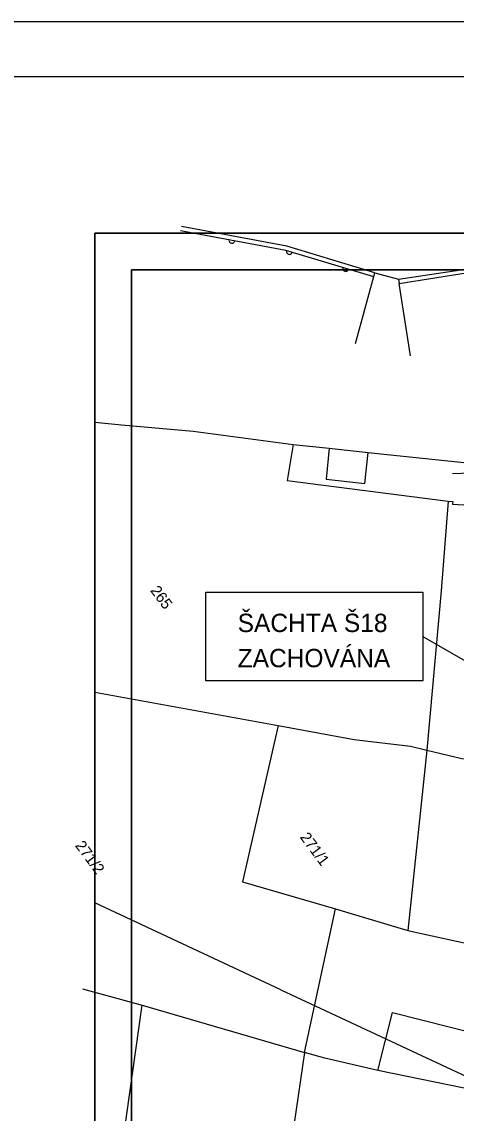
# Model space of a CAD drawing. Extents: x -601580 to 4, y -1204314 to 4.
# Drawn here: x -596081 to -596051.4, y -1202950 to -1202875.6 of the extents above; entities that cross this region are included whole.
import ezdxf

# ---------------------------------------------------------------- set-up
doc = ezdxf.new("R2010")
doc.units = 0
for name, color, linetype in [('00-KN-HRANICE PARCEL', 7, 'Continuous'), ('00-KN-PARC. CISLA', 7, 'Continuous'), ('00-KN-VNITRNI KRESBA', 7, 'Continuous'), ('00-POLOHOPIS', 7, 'Continuous'), ('00-RAZÍTKO', 7, 'Continuous'), ('00-SITE KOM. KABEL', 7, 'Continuous'), ('11-REKONSTRUKCE KANALIZACE', 7, 'Continuous'), ('11-REKONSTRUKCE KANALIZACE OSA', 7, 'Continuous')]:
    doc.layers.add(name, color=color, linetype=linetype)

msp = doc.modelspace()

# ---------------------------------------------------------------- linework, layer by layer
for points in [[(-595979.871, -1202875.568), (-596202.621, -1202875.568), (-596202.621, -1203190.718), (-595979.871, -1203190.718)], [(-595976.121, -1202879.318), (-596198.871, -1202879.318), (-596198.871, -1203186.968), (-595976.121, -1203186.968)], [(-595970.972, -1202892.468), (-595970.972, -1202889.968), (-596076.023, -1202889.968), (-596076.023, -1203038.468), (-595970.972, -1203038.468), (-595970.972, -1203035.968)], [(-595973.472, -1202892.468), (-596073.523, -1202892.468), (-596073.523, -1203035.968), (-595973.472, -1203035.968)]]:
    msp.add_lwpolyline(points)
at = {"layer": '00-KN-HRANICE PARCEL'}
for p, q in [((-596076.023, -1202921.275), (-596063.515, -1202923.548)), ((-596053.37, -1202925.22), (-596054.675, -1202937.522)), ((-596061.708, -1202945.831), (-596059.607, -1202936.028)), ((-596059.607, -1202936.028), (-596054.675, -1202937.522)), ((-596054.675, -1202937.522), (-596044.06, -1202939.843)), ((-596076.023, -1202965.353), (-596072.776, -1202942.614)), ((-596072.776, -1202942.614), (-596061.708, -1202945.831))]:
    msp.add_line(p, q, dxfattribs=at)
for points in [[(-596076.023, -1202902.865), (-596074.192, -1202903.041), (-596069.318, -1202903.483), (-596062.496, -1202904.385)], [(-596062.496, -1202904.385), (-596062.908, -1202906.833), (-596051.923, -1202908.243), (-596052.392, -1202914.357), (-596053.37, -1202925.22)], [(-596062.496, -1202904.385), (-596060.039, -1202904.641), (-596057.379, -1202904.92), (-596046.724, -1202906.053)], [(-596063.515, -1202923.548), (-596065.954, -1202934.188), (-596059.607, -1202936.028)], [(-596063.515, -1202923.548), (-596058.322, -1202924.488), (-596054.488, -1202924.955), (-596053.37, -1202925.22)], [(-596053.37, -1202925.22), (-596050.98, -1202925.788), (-596050.546, -1202925.802), (-596039.898, -1202926.205)], [(-596076.855, -1202941.482), (-596072.776, -1202942.614)], [(-596061.708, -1202945.831), (-596062.42, -1202950.644), (-596063.31, -1202962.65), (-596063.999, -1202967.022)]]:
    msp.add_lwpolyline(points, dxfattribs=at)
at = {"layer": '00-KN-VNITRNI KRESBA'}
for p, q in [((-596056.706, -1202947.05), (-596055.708, -1202943.109)), ((-596055.708, -1202943.109), (-596049.141, -1202944.76)), ((-596060.33, -1202946.228), (-596061.708, -1202945.831)), ((-596056.706, -1202947.05), (-596060.33, -1202946.228)), ((-596049.949, -1202948.436), (-596056.706, -1202947.05))]:
    msp.add_line(p, q, dxfattribs=at)
for points in [[(-596060.039, -1202904.641), (-596060.238, -1202906.756), (-596057.605, -1202907.031), (-596057.379, -1202904.92)], [(-596051.923, -1202908.243), (-596051.599, -1202908.277), (-596051.618, -1202908.453), (-596046.224, -1202908.758)]]:
    msp.add_lwpolyline(points, dxfattribs=at)
at = {"layer": '00-POLOHOPIS'}
for p, q in [((-596055.312, -1202893.112), (-596048.042, -1202892.011)), ((-596055.266, -1202893.408), (-596047.533, -1202892.187)), ((-596058.247, -1202897.489), (-596056.918, -1202892.669)), ((-596056.918, -1202892.669), (-596055.312, -1202893.112)), ((-596055.312, -1202893.112), (-596055.266, -1202893.408)), ((-596054.487, -1202898.347), (-596055.266, -1202893.408)), ((-596051.63, -1202906.351), (-596046.632, -1202906.22))]:
    msp.add_line(p, q, dxfattribs=at)
for points in [[(-596056.998, -1202892.959), (-596062.989, -1202891.147), (-596070.167, -1202889.808)], [(-596056.998, -1202892.959), (-596062.989, -1202891.147), (-596070.167, -1202889.808)], [(-596056.918, -1202892.669), (-596062.918, -1202890.856), (-596070.112, -1202889.513)]]:
    msp.add_lwpolyline(points, dxfattribs=at)
for centre, start, end in [((-596066.667, -1202890.461), 169.42499, 349.42786), ((-596062.741, -1202891.222), 163.1773, 343.18017), ((-596058.913, -1202892.38), 163.1773, 343.18017)]:
    msp.add_arc(centre, 0.2, start, end, dxfattribs=at)
at = {"layer": '00-RAZÍTKO'}
for points in [[(-596076.023, -1202889.968), (-595760.871, -1202889.968), (-595760.871, -1203038.468), (-596076.023, -1203038.468)], [(-596073.523, -1202892.468), (-595763.371, -1202892.468), (-595763.371, -1203035.968), (-596073.523, -1203035.968)]]:
    msp.add_lwpolyline(points, close=True, dxfattribs=at)
at = {"layer": '00-SITE KOM. KABEL'}
for points in [[(-596063.34, -1202941.557), (-596076.023, -1202935.637)], [(-596063.341, -1202941.557), (-596047.937, -1202948.748)]]:
    msp.add_lwpolyline(points, dxfattribs=at)
at = {"layer": '11-REKONSTRUKCE KANALIZACE'}
msp.add_line((-596053.64, -1202917.472), (-596034.151, -1202928.711), dxfattribs=at)
msp.add_lwpolyline([(-596068.439, -1202914.456), (-596053.64, -1202914.456), (-596053.64, -1202920.488), (-596068.439, -1202920.488)], close=True, dxfattribs=at)

# ---------------------------------------------------------------- texts
at = {"layer": '00-KN-PARC. CISLA'}
for s, p in [('265', (-596072.264, -1202914.346)), ('271/1', (-596062.06, -1202931.162)), ('271/2', (-596077.392, -1202931.731))]:
    msp.add_text(s, height=0.75, rotation=306.58532, dxfattribs=at).set_placement(p)
at = {"layer": '11-REKONSTRUKCE KANALIZACE OSA'}
for s, p in [('ŠACHTA Š18  ', (-596066.274, -1202917.17)), ('ZACHOVÁNA', (-596066.274, -1202919.569))]:
    msp.add_text(s, height=1.25, dxfattribs=at).set_placement(p)

doc.saveas('drawing.dxf')
